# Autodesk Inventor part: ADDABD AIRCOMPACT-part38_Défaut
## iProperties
Shininess: 64.0
Length Units: 11269
Angle Units: 11279
Time Units: 11290
Mass Units: 11283
Length Display Precision: 3
Angle Display Precision: 2
Compacted: True
Part Number: ADDABD AIRCOMPACT-part38_Défaut
Document SubType Name: Modeling
Created: 2006-01
Material: Par défaut
Designer: riri
Density: 0.0
Volumn: 0.0
Area: 0.0
PropertySet Name: Model Information
Control State: 0
Master: False
Checked Out: False
Author: riri
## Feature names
1. Base1
